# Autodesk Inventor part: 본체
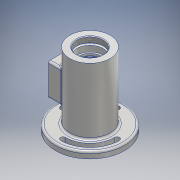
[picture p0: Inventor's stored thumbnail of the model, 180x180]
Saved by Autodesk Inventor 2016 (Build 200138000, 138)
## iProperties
Created: 2017-05
Part Number: 본체
Material: 알루미늄 6061
Document SubType Name: Modeling
Designer: USER
Density: 2.7 g/cm^3
Appearance: 알루미늄 - 평지
Mass: 677.06 g
Surface Area: 624.507 cm^2
Volume: 250.763 cm^3
Author: USER
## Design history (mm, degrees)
sketch "스케치1"
  geometry: C1 r 31 at (0, 0); 1 further point
  constraints: 1 centre point, 1 coincident
  dimensions: "d0" = 62 diameter of C1
extrude "돌출1" new body sketch "스케치1" distance "d1" = 115; taper "d2" = 0 deg
node "작업 평면1"
sketch "스케치2"
  geometry: C1 r 53 at (0, 0); 1 further point
  constraints: 1 centre point, 1 coincident
  dimensions: "d4" = 106 diameter of C1
extrude "돌출2" join sketch "스케치2" distance "d5" = 10; taper "d6" = 0 deg
sketch "스케치3"
  geometry: 1 further point
hole "구멍1" sketch "스케치3" at (0, 0) diameter "d7" = 40.376; stored, may be unused: countersink angle "d11" = 90 deg, drill point angle "d13" = 118 deg; dims "d8" = 9, "d9" = 4, "d10" = 2, "d12" = 9
node "작업 평면2"
sketch "스케치4"
  geometry: L1 (-20.188, 115)-(20.188, 115) reference; L2 (-31, 0)-(31, 0) reference; L3 (0, 115)-(0, 0); L4 (20.188, 106)-(-20.188, 106) reference; L5 (0, 106)-(24, 106); L6 (24, 106)-(24, 103); L7 (24, 103)-(20, 103); L8 (20, 103)-(20, 94); L9 (20, 94)-(17.5, 94); L10 (17.5, 94)-(17.5, 90.75); L11 (17.5, 90.75)-(18.5, 90.75); L12 (18.5, 89)-(17.5, 89); L13 (17.5, 89)-(17.5, 78); L14 (17.5, 78)-(26, 78); L15 (26, 78)-(26, 40); L16 (26, 40)-(17.5, 40); L17 (17.5, 40)-(17.5, 29.3); L18 (17.2, 29)-(16.5, 29); L19 (16.5, 29)-(16.5, 27); L20 (13.5, 24)-(10, 24); L21 (10, 24)-(10, 21.3); L22 (17.255, 11.828)-(22, 0); L23 (18.5, 90.75)-(18.5, 89); L24 (10, 21.3)-(12.2, 21.3); L25 (12.5, 21)-(12.5, 14.411); L26 (31, 13)-(-31, 13) reference; L27 (12.904, 13.711)-(14.471, 13.711); L28 (12.5, 14.411)-(0, 14.411); L29 (12.5, 14.411)-(12.904, 13.711); A1 r 0.3 centre (12.2, 21) between (12.5, 21) and (12.2, 21.3); A2 r 3 centre (13.5, 27) between (13.5, 24) and (16.5, 27); A3 r 3 centre (14.471, 10.711) between (17.255, 11.828) and (14.471, 13.711); A4 r 0.3 centre (17.2, 29.3) between (17.2, 29) and (17.5, 29.3); 4 further points
  constraints: 50 end point, 14 perpendicular, 12 point on line, 8 point on circle, 8 tangent, 6 horizontal, 4 centre point, 2 midpoint, 2 vertical
  dimensions: "d15" = 3 distance of L5.end L6.end; "d16" = 21 distance between parallel lines of L9 L1; "d17" = 38 distance between parallel lines of L16 L14; "d19" = 11 distance of L16.end point (17.5, 29); "d20" = 5 distance of L18.end point (16.5, 24); "d21" = 24 vertical distance of L22.end point (16.5, 24); "d23" = 1.75 distance of L11.end L12.start; "d24" = 26 distance between parallel lines of L12 L1; "d25" = 48 diameter of L6 L3; "d26" = 40 diameter of L8 L3; "d27" = 35 diameter of L10 L3; "d28" = 37 diameter of L23 L3; "d29" = 35 diameter of L13 L3; "d30" = 52 diameter of L15 L3; "d31" = 35 diameter of L17 L3; "d32" = 33 diameter of L19 L3; "d33" = 20 diameter of L21 L3; "d34" = 25 diameter of L25 L3; "d37" = 44 diameter of L22.end L3; "d38" = 0.3 radius of A1; "d39" = 3 radius of A2; "d40" = 7.3 distance of L25.start L27.start; "d41" = 2.7 distance of L20.end L21.end; "d42" = 3 radius of A3; "d87" = 0.3 radius of A4; "d88" = 0.7 distance between parallel lines of L27 L28; "d89" = 30 deg angle of L25 L29
revolve "회전1" stored, may be unused: angle "d43" = 90 deg
node "작업 평면3"
sketch "스케치5"
  geometry: L1 (31, 115)-(-31, 115) reference; L2 (53, 13)-(-53, 13) reference; L3 (20, 84)-(-20, 84); L4 (-20, 84)-(-20, 34); L5 (-20, 34)-(20, 34); L6 (20, 34)-(20, 84); L7 (20, 84)-(-20, 34); L8 (-20, 84)-(20, 34); L9 (11, 75)-(-11, 75); L10 (-11, 75)-(-11, 43); L11 (-11, 43)-(11, 43); L12 (11, 43)-(11, 75); L13 (11, 75)-(-11, 43); L14 (-11, 75)-(11, 43); 4 further points
  constraints: 24 end point, 6 midpoint, 4 parallel, 2 horizontal, 2 perpendicular, 1 vertical alignment
  dimensions: "d45" = 56 distance from line of point (0, 59) L1; "d46" = 40 distance between parallel lines of L6 L4; "d47" = 50 distance between parallel lines of L5 L3; "d48" = 22 distance of L10.end L11.end; "d49" = 32 distance of L11.end L9.start
extrude "돌출3" join sketch "스케치5" stored distance "d50" = 10; taper "d51" = 0 deg
sketch "스케치6"
  geometry: 1 further point
extrude "돌출4" cut sketch "스케치5" distance "d52" = 20; taper "d53" = 0 deg
sketch "스케치7"
  geometry: L1 (84, 20)-(84, -20) reference; L2 (75, 11)-(75, -11) reference; L3 (115, -31)-(115, 31) reference; L4 (13, -31)-(13, 31) reference; L5 (34, 20)-(84, 20) reference; L6 (84, 20)-(84, -20) reference; L7 (84, -20)-(34, -20) reference; L8 (34, -20)-(34, 20) reference; 5 further points
  dimensions: "d54" = 41 distance of point (38.5, -15.358) point (79.5, -15.5); "d56" = 15.5 vertical distance of point (0, 0) point (79.5, -15.5); "d57" = 4.5 distance from line of point (79.5, -15.5) L1; "d58" = 31 distance of point (38.5, 15.642) point (38.5, -15.358); "d59" = 41 distance of point (38.5, 15.642) point (79.5, 15.5); "d60" = 31 distance of point (79.5, 15.5) point (79.5, -15.5); "d61" = 4.5 distance from line of point (79.5, 15.5) L1; "d62" = 4.50024 distance from line of L8 point (38.5, -15.358)
  node "투영된 루프1"
hole "구멍2" sketch "스케치7" diameter "d63" = 2.459; stored, may be unused: countersink angle "d67" = 90 deg, drill point angle "d69" = 118 deg; dims "d64" = 6, "d65" = 4, "d66" = 2, "d68" = 8
hole "구멍3" sketch "스케치7" diameter "d70" = 2.459; stored, may be unused: countersink angle "d74" = 90 deg, drill point angle "d76" = 118 deg; dims "d71" = 6, "d72" = 4, "d73" = 2, "d75" = 8
sketch "스케치8"
  geometry: L1 (0, 0)-(53, 0); C1 r 31 at (0, 0) reference; A1 r 41.5 centre (0, 0) between (41.5, 0) and (0, 41.5); A2 r 4 centre (41.5, 0) between (37.5, 0) and (45.5, 0); A3 r 4 centre (0, 41.5) between (0, 45.5) and (0, 37.5); A4 r 4 centre (0, -41.5) between (0, -45.5) and (0, -37.5); A5 r 4 centre (-41.5, 0) between (-37.5, 0) and (-45.5, 0); A6 r 37.5 centre (0, 0) between (-37.5, 0) and (0, -37.5); A7 r 37.5 centre (0, 0) between (37.5, 0) and (0, 37.5); A8 r 45.5 centre (0, 0) between (-45.5, 0) and (0, -45.5); A9 r 45.5 centre (0, 0) between (45.5, 0) and (0, 45.5); 2 further points
  constraints: 20 point on circle, 9 centre point, 3 coincident, 3 point on line, 2 end point, 2 horizontal alignment, 2 vertical alignment, 1 horizontal, 1 tangent, 1 other
  dimensions: "d77" = 83 diameter of A1; "d80" = 8 diameter of A2; "d81" = 8 diameter of A3; "d82" = 8 diameter of A4; "d83" = 8 diameter of A5; "d84" = 8 radial gap between concentric circles of A8 A6
extrude "돌출5" cut sketch "스케치8" stored distance "d85" = 20; taper "d86" = 0 deg
fillet "모깎기1" dims "d90" = 3
fillet "모깎기2" dims "d91" = 3
chamfer "모따기1" distance "d93" = 1; stored, may be unused: second distance "d94" = 2, angle "d95" = 45 deg
fillet "모깎기4" dims "d96" = 3
fillet "모깎기5" dims "d97" = 3
sketch "스케치9"
  geometry: 1 further point
node "작업 평면4"
sketch "스케치10"
  geometry: L1 (13, -34)-(75, -34) reference; L2 (0, 44)-(0, 0) reference; 2 further points
  constraints: 1 other
  dimensions: "d99" = 56 distance from line of point (8, 22) L1; "d100" = 8 distance from line of L2 point (8, 22)
feature "엠보싱1" sketch "스케치10" dims "d0" = 62, "d101" = 0.5, "d102" = 0
sketch "스케치11"
  geometry: L1 (53, 10)-(53, 3) reference; L2 (53, 3)-(45.5, 3) reference; L3 (45.5, 3)-(45.5, 13) reference; L4 (45.5, 13)-(50, 13) reference; L5 (-50, 13)-(-45.5, 13) reference; L6 (-45.5, 13)-(-45.5, 3) reference; L7 (-45.5, 3)-(-53, 3) reference; L8 (-53, 3)-(-53, 10) reference; L9 (17.5, 78)-(17.5, 89) reference; L10 (17.5, 89)-(18.5, 89) reference; L11 (18.5, 89)-(18.5, 90.75) reference; L12 (18.5, 90.75)-(17.5, 90.75) reference; L13 (17.5, 90.75)-(17.5, 94) reference; L14 (17.5, 94)-(20, 94) reference; L15 (20, 94)-(20, 103) reference; L16 (20, 103)-(24, 103) reference; L17 (24, 103)-(24, 106) reference; L18 (24, 106)-(20.188, 106) reference; L19 (20.188, 106)-(20.188, 114) reference; L20 (20.188, 114)-(21.188, 115) reference; L21 (21.188, 115)-(31, 115) reference; L22 (31, 115)-(31, 87) reference; L23 (34, 84)-(44, 84) reference; L24 (44, 84)-(44, 75) reference; L25 (44, 75)-(26, 75) reference; L26 (26, 75)-(26, 78) reference; L27 (26, 78)-(17.5, 78) reference; L28 (-12.5, 14.411)-(12.5, 14.411) reference; L29 (12.5, 14.411)-(12.5, 21) reference; L30 (12.2, 21.3)-(10, 21.3) reference; L31 (10, 21.3)-(10, 24) reference; L32 (10, 24)-(13.5, 24) reference; L33 (16.5, 27)-(16.5, 29) reference; L34 (16.5, 29)-(17.2, 29) reference; L35 (17.5, 29.3)-(17.5, 40) reference; L36 (17.5, 40)-(26, 40) reference; L37 (26, 40)-(26, 43) reference; L38 (26, 43)-(44, 43) reference; L39 (44, 43)-(44, 34) reference; L40 (44, 34)-(34, 34) reference; L41 (31, 31)-(31, 16) reference; L42 (34, 13)-(37.5, 13) reference; L43 (37.5, 13)-(37.5, 3) reference; L44 (37.5, 3)-(31, 3) reference; L45 (31, 3)-(31, 0) reference; L46 (31, 0)-(-31, 0) reference; L47 (-31, 0)-(-31, 3) reference; L48 (-31, 3)-(-37.5, 3) reference; L49 (-37.5, 3)-(-37.5, 13) reference; L50 (-37.5, 13)-(-34, 13) reference; L51 (-31, 16)-(-31, 115) reference; L52 (-31, 115)-(-21.188, 115) reference; L53 (-21.188, 115)-(-20.188, 114) reference; L54 (-20.188, 114)-(-20.188, 106) reference; L55 (-20.188, 106)-(-24, 106) reference; L56 (-24, 106)-(-24, 103) reference; L57 (-24, 103)-(-20, 103) reference; L58 (-20, 103)-(-20, 94) reference; L59 (-20, 94)-(-17.5, 94) reference; L60 (-17.5, 94)-(-17.5, 90.75) reference; L61 (-17.5, 90.75)-(-18.5, 90.75) reference; L62 (-18.5, 90.75)-(-18.5, 89) reference; L63 (-18.5, 89)-(-17.5, 89) reference; L64 (-17.5, 89)-(-17.5, 78) reference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; A1 r 3 centre (50, 10) between (53, 10) and (50, 13) reference; A2 r 3 centre (-50, 10) between (-50, 13) and (-53, 10) reference; A3 r 3 centre (34, 87) between (31, 87) and (34, 84) reference; A4 r 0.3 centre (12.2, 21) between (12.5, 21) and (12.2, 21.3) reference; A5 r 3 centre (13.5, 27) between (13.5, 24) and (16.5, 27) reference; A6 r 0.3 centre (17.2, 29.3) between (17.2, 29) and (17.5, 29.3) reference; A7 r 3 centre (34, 31) between (34, 34) and (31, 31) reference; A8 r 3 centre (34, 16) between (31, 16) and (34, 13) reference; A9 r 3 centre (-34, 16) between (-34, 13) and (-31, 16) reference; A10 r 0.3 centre (-17.2, 29.3) between (-17.5, 29.3) and (-17.2, 29) reference; A11 r 3 centre (-13.5, 27) between (-16.5, 27) and (-13.5, 24) reference; A12 r 0.3 centre (-12.2, 21) between (-12.2, 21.3) and (-12.5, 21) reference; 1 further point
  node "절단 모서리 투영1"
sketch "스케치12"
  geometry: 1 further point
revolve "회전2" stored, may be unused: angle "d103" = 90 deg
fillet "모깎기6" dims "d104" = 3
fillet "모깎기8" dims "d106" = 3
chamfer "모따기2" distance "d107" = 1; stored, may be unused: second distance "d108" = 2, angle "d109" = 45 deg
node "솔리드1"
node "투영된 루프2"
other parameters: "d3" = -3, "d14" = 0, "d44" = -44, "d78" = 75, "d79" = 91, "d98" = 18.25
